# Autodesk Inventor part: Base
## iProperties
Created: 2002-02
Part Number: Base
Document SubType Name: Modeling
Designer: ***
Control State: 0
Master: False
Checked Out: False
Shininess: 77.0
Length Units: 11269
Angle Units: 11279
Time Units: 11290
Mass Units: 11283
Length Display Precision: 3
Angle Display Precision: 2
Density: 0.0
Volumn: 0.0
Area: 0.0
PropertySet Name: Model Information
Author: ***
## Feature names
1. Extrusion1
2. Extrusion2
3. Extrusion3
4. Hole1
5. Mirror1
6. Extrusion4
7. Extrusion5
